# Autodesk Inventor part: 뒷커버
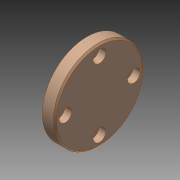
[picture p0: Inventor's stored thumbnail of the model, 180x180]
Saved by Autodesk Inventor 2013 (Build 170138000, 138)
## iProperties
Created: 2024-01
Part Number: 뒷커버
Material: 알루미늄 6061
Document SubType Name: Modeling
Designer: mdu-01
Density: 1 g/cm^3
Author: mdu-01
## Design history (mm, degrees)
sketch "스케치1"
  geometry: L1 (0, 0)-(-9, 0); L2 (-9, 0)-(-9, 14.5); L3 (-9, 14.5)-(-12, 14.5); L4 (-12, 14.5)-(-12, 16.5); L5 (-11, 17.5)-(-8, 17.5); L6 (-8, 17.5)-(-8, 28); L7 (-8, 28)-(-1, 28); L8 (0, 27)-(0, 0); L9 (-12, 16.5)-(-11, 17.5); L10 (-1, 28)-(0, 27); 2 further points
  constraints: 20 end point, 6 parallel, 4 point on line, 1 horizontal, 1 perpendicular
  dimensions: "d0" = 56 diameter of L7 L1; "d2" = 8 distance between parallel lines of L8 L6; "d3" = 3 distance between parallel lines of L2 L4; "d4" = 4 distance between parallel lines of L6 L4; "d5" = 29 diameter of L3 L1; "d6" = 35 diameter of L5 L1; "d7" = 1 distance of L4.end point (-12, 17.5); "d8" = 1 distance of L5.start point (-12, 17.5) (= d7); "d9" = 1 distance of L7.end point (0, 28) (= d7); "d10" = 1 distance of L8.start point (0, 28) (= d9)
revolve "회전1" sketch "스케치1" stored, may be unused: angle "d11" = 90 deg
sketch "스케치2" dims "d12" = 43
  geometry: 3 further points
  constraints: 2 vertical alignment, 1 coincident, 2 other
hole "구멍1" sketch "스케치2" at (0, 21.5) diameter "d13" = 4.5; stored, may be unused: countersink angle "d17" = 90 deg, drill point angle "d19" = 118 deg; dims "d14" = 6, "d15" = 8, "d16" = 4.4, "d18" = 8
node "솔리드1"
pattern_circular "원형 패턴1" dims angle "d21" = 360 deg
